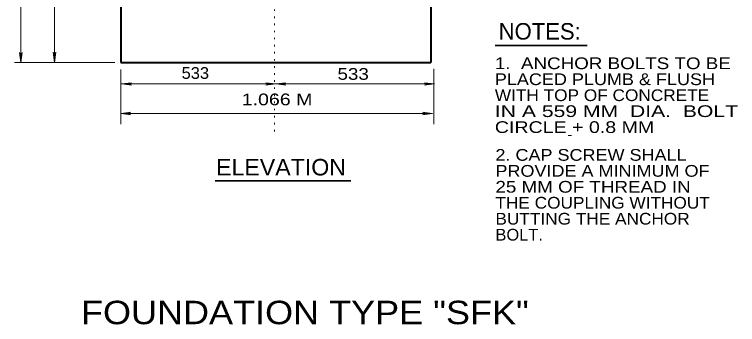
# Model space of a CAD drawing. Extents: x 312583 to 312854, y 144419 to 144597.
# Drawn here: x 312760.59 to 312807.52, y 144472.67 to 144492.78 of the extents above; entities that cross this region are included whole.
import ezdxf
from ezdxf.enums import TextEntityAlignment as Align

# ---------------------------------------------------------------- set-up
doc = ezdxf.new("R2010")
doc.units = 0
doc.header["$LTSCALE"] = 0.3
doc.linetypes.add('DOTTED', pattern=[1.5, 0.3, -1.2])
doc.layers.add('1', color=7, linetype='Continuous', lineweight=25)
doc.layers.add('2', color=7, linetype='Continuous', lineweight=13)

msp = doc.modelspace()

# ---------------------------------------------------------------- linework, layer by layer
at = {"layer": '1', "lineweight": 40}
for p, q in [((312767.4871, 144512.6744), (312767.4871, 144489.6744)), ((312787.6121, 144512.6744), (312787.6121, 144489.6744)), ((312767.4871, 144489.6744), (312787.6121, 144489.6744))]:
    msp.add_line(p, q, dxfattribs=at)
at = {"layer": '1', "lineweight": 35}
msp.add_line((312791.7958, 144490.7584), (312797.753, 144490.7584), dxfattribs=at)
at = {"layer": '2', "linetype": 'DOTTED'}
msp.add_line((312777.4691, 144485.1894), (312777.4691, 144522.3114), dxfattribs=at)
at = {"layer": '2'}
for p, q in [((312761.0011, 144489.6667), (312761.0011, 144518.4244)), ((312760.9168, 144490.3107), (312761.0011, 144490.1037)), ((312761.0011, 144489.6667), (312760.9168, 144490.3107)), ((312761.0778, 144490.3107), (312761.0011, 144490.1037)), ((312761.0011, 144489.6667), (312761.0778, 144490.3107)), ((312763.1095, 144490.326), (312763.1861, 144490.119)), ((312763.1861, 144489.6744), (312763.1095, 144490.326)), ((312763.2705, 144490.326), (312763.1861, 144490.119)), ((312763.1861, 144489.6744), (312763.2705, 144490.326)), ((312767.1038, 144489.6744), (312760.5871, 144489.6744)), ((312767.4871, 144485.6724), (312767.4871, 144489.2067)), ((312787.8115, 144485.6724), (312787.8115, 144489.2527)), ((312767.5331, 144488.2714), (312768.1848, 144488.3557)), ((312777.5535, 144488.2714), (312767.5331, 144488.2714)), ((312767.5331, 144488.2714), (312768.1848, 144488.1947)), ((312768.1848, 144488.3557), (312767.9778, 144488.2714)), ((312768.1848, 144488.1947), (312767.9778, 144488.2714)), ((312776.9018, 144488.3557), (312777.1088, 144488.2714)), ((312777.5535, 144488.2714), (312776.9018, 144488.3557)), ((312776.9018, 144488.1947), (312777.1088, 144488.2714)), ((312777.5535, 144488.2714), (312776.9018, 144488.1947)), ((312777.5535, 144488.2714), (312778.1975, 144488.3557)), ((312787.8575, 144488.2714), (312777.5535, 144488.2714)), ((312777.5535, 144488.2714), (312778.1975, 144488.1947)), ((312778.1975, 144488.3557), (312777.9905, 144488.2714)), ((312778.1975, 144488.1947), (312777.9905, 144488.2714)), ((312787.2058, 144488.3557), (312787.4128, 144488.2714)), ((312787.8575, 144488.2714), (312787.2058, 144488.3557)), ((312787.2058, 144488.1947), (312787.4128, 144488.2714)), ((312787.8575, 144488.2714), (312787.2058, 144488.1947)), ((312767.4871, 144486.3547), (312768.1388, 144486.439)), ((312787.7271, 144486.3547), (312767.4871, 144486.3547)), ((312767.4871, 144486.3547), (312768.1388, 144486.278)), ((312768.1388, 144486.439), (312767.9318, 144486.3547)), ((312768.1388, 144486.278), (312767.9318, 144486.3547)), ((312787.0755, 144486.439), (312787.2825, 144486.3547)), ((312787.7271, 144486.3547), (312787.0755, 144486.439)), ((312787.0755, 144486.278), (312787.2825, 144486.3547)), ((312787.7271, 144486.3547), (312787.0755, 144486.278))]:
    msp.add_line(p, q, dxfattribs=at)
at = {"layer": '2', "lineweight": 35}
msp.add_line((312782.4122, 144481.993), (312773.6118, 144481.993), dxfattribs=at)
at = {"layer": '2'}
msp.add_lwpolyline([(312763.1861, 144489.6744), (312763.1861, 144512.6744), (312763.1861, 144518.4244)], dxfattribs=at)

# ---------------------------------------------------------------- texts
msp.add_text('NOTES:', height=1.07, dxfattribs=at).set_placement((312794.677, 144491.1521), align=Align.CENTER)
for s, width, p in [('1.  ANCHOR BOLTS TO BE', 1.2, (312791.7652, 144489.2346)), ('533', 1.05, (312771.4359, 144488.6037)), ('533 ', 1.2, (312781.5529, 144488.5428)), ('PLACED PLUMB & FLUSH', 1.15, (312791.7652, 144488.1996)), ('1.066 M', 1.25, (312775.3358, 144486.8921)), ('WITH TOP OF CONCRETE', 1.1, (312791.7652, 144487.1646)), ('IN A 559 MM  DIA.  BOLT ', 1.35, (312791.7652, 144486.1296)), ('CIRCLE + 0.8 MM', 1.25, (312791.7652, 144485.0946)), ('2. CAP SCREW SHALL', 1.15, (312791.8035, 144483.2929)), ('PROVIDE A MINIMUM OF', 1.15, (312791.8035, 144482.2579)), ('25 MM OF THREAD IN', 1.2, (312791.8035, 144481.2229)), ('THE COUPLING WITHOUT', 1.1, (312791.8035, 144480.1879)), ('BUTTING THE ANCHOR', 1.1, (312791.8035, 144479.1529)), ('BOLT.', 1.05, (312791.8035, 144478.1179))]:
    msp.add_text(s, height=0.76, dxfattribs=dict(at, width=width)).set_placement(p)
msp.add_text('-', height=0.69, dxfattribs=at).set_placement((312796.4775, 144484.663))
for s, height, width, p in [('ELEVATION', 1.07, 1.05, (312777.8871, 144482.3408)), ('FOUNDATION TYPE "SFK"', 1.52, 1.15, (312779.4361, 144472.6932))]:
    msp.add_text(s, height=height, dxfattribs=dict(at, width=width)).set_placement(p, align=Align.CENTER)

doc.saveas('drawing.dxf')
